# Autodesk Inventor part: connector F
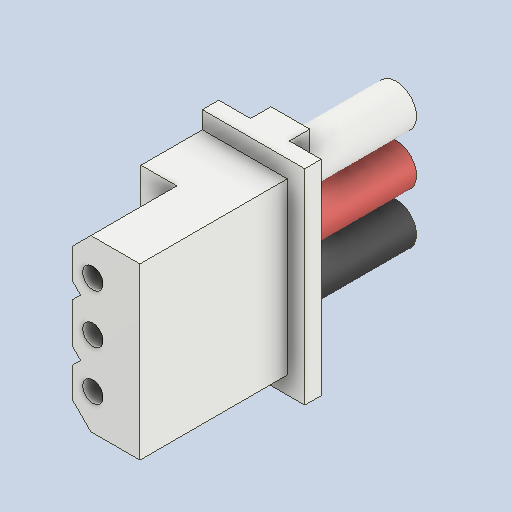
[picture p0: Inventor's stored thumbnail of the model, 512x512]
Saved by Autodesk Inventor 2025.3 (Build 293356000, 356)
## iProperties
Created: 2026-10
Part Number: connector F
Material: Acier
Document SubType Name: Modeling
Designer: Luis M
Density: 7.85 g/cm^3
Appearance: Valor por defecto
Author: Luis M
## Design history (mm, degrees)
feature "Corps1"
node "Sólido1"
